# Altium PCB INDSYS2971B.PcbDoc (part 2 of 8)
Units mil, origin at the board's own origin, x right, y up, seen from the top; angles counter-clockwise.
Board outline 6450 x 5820 mil, 6 copper layers (Top Layer, Int1 (PGND), Int2 (AGND), Int3 (Signal), Int4 (PGND), Bottom Layer), stack 70.536 mil thick; 787 components, 431 nets, 2530 pads, 2497 vias.
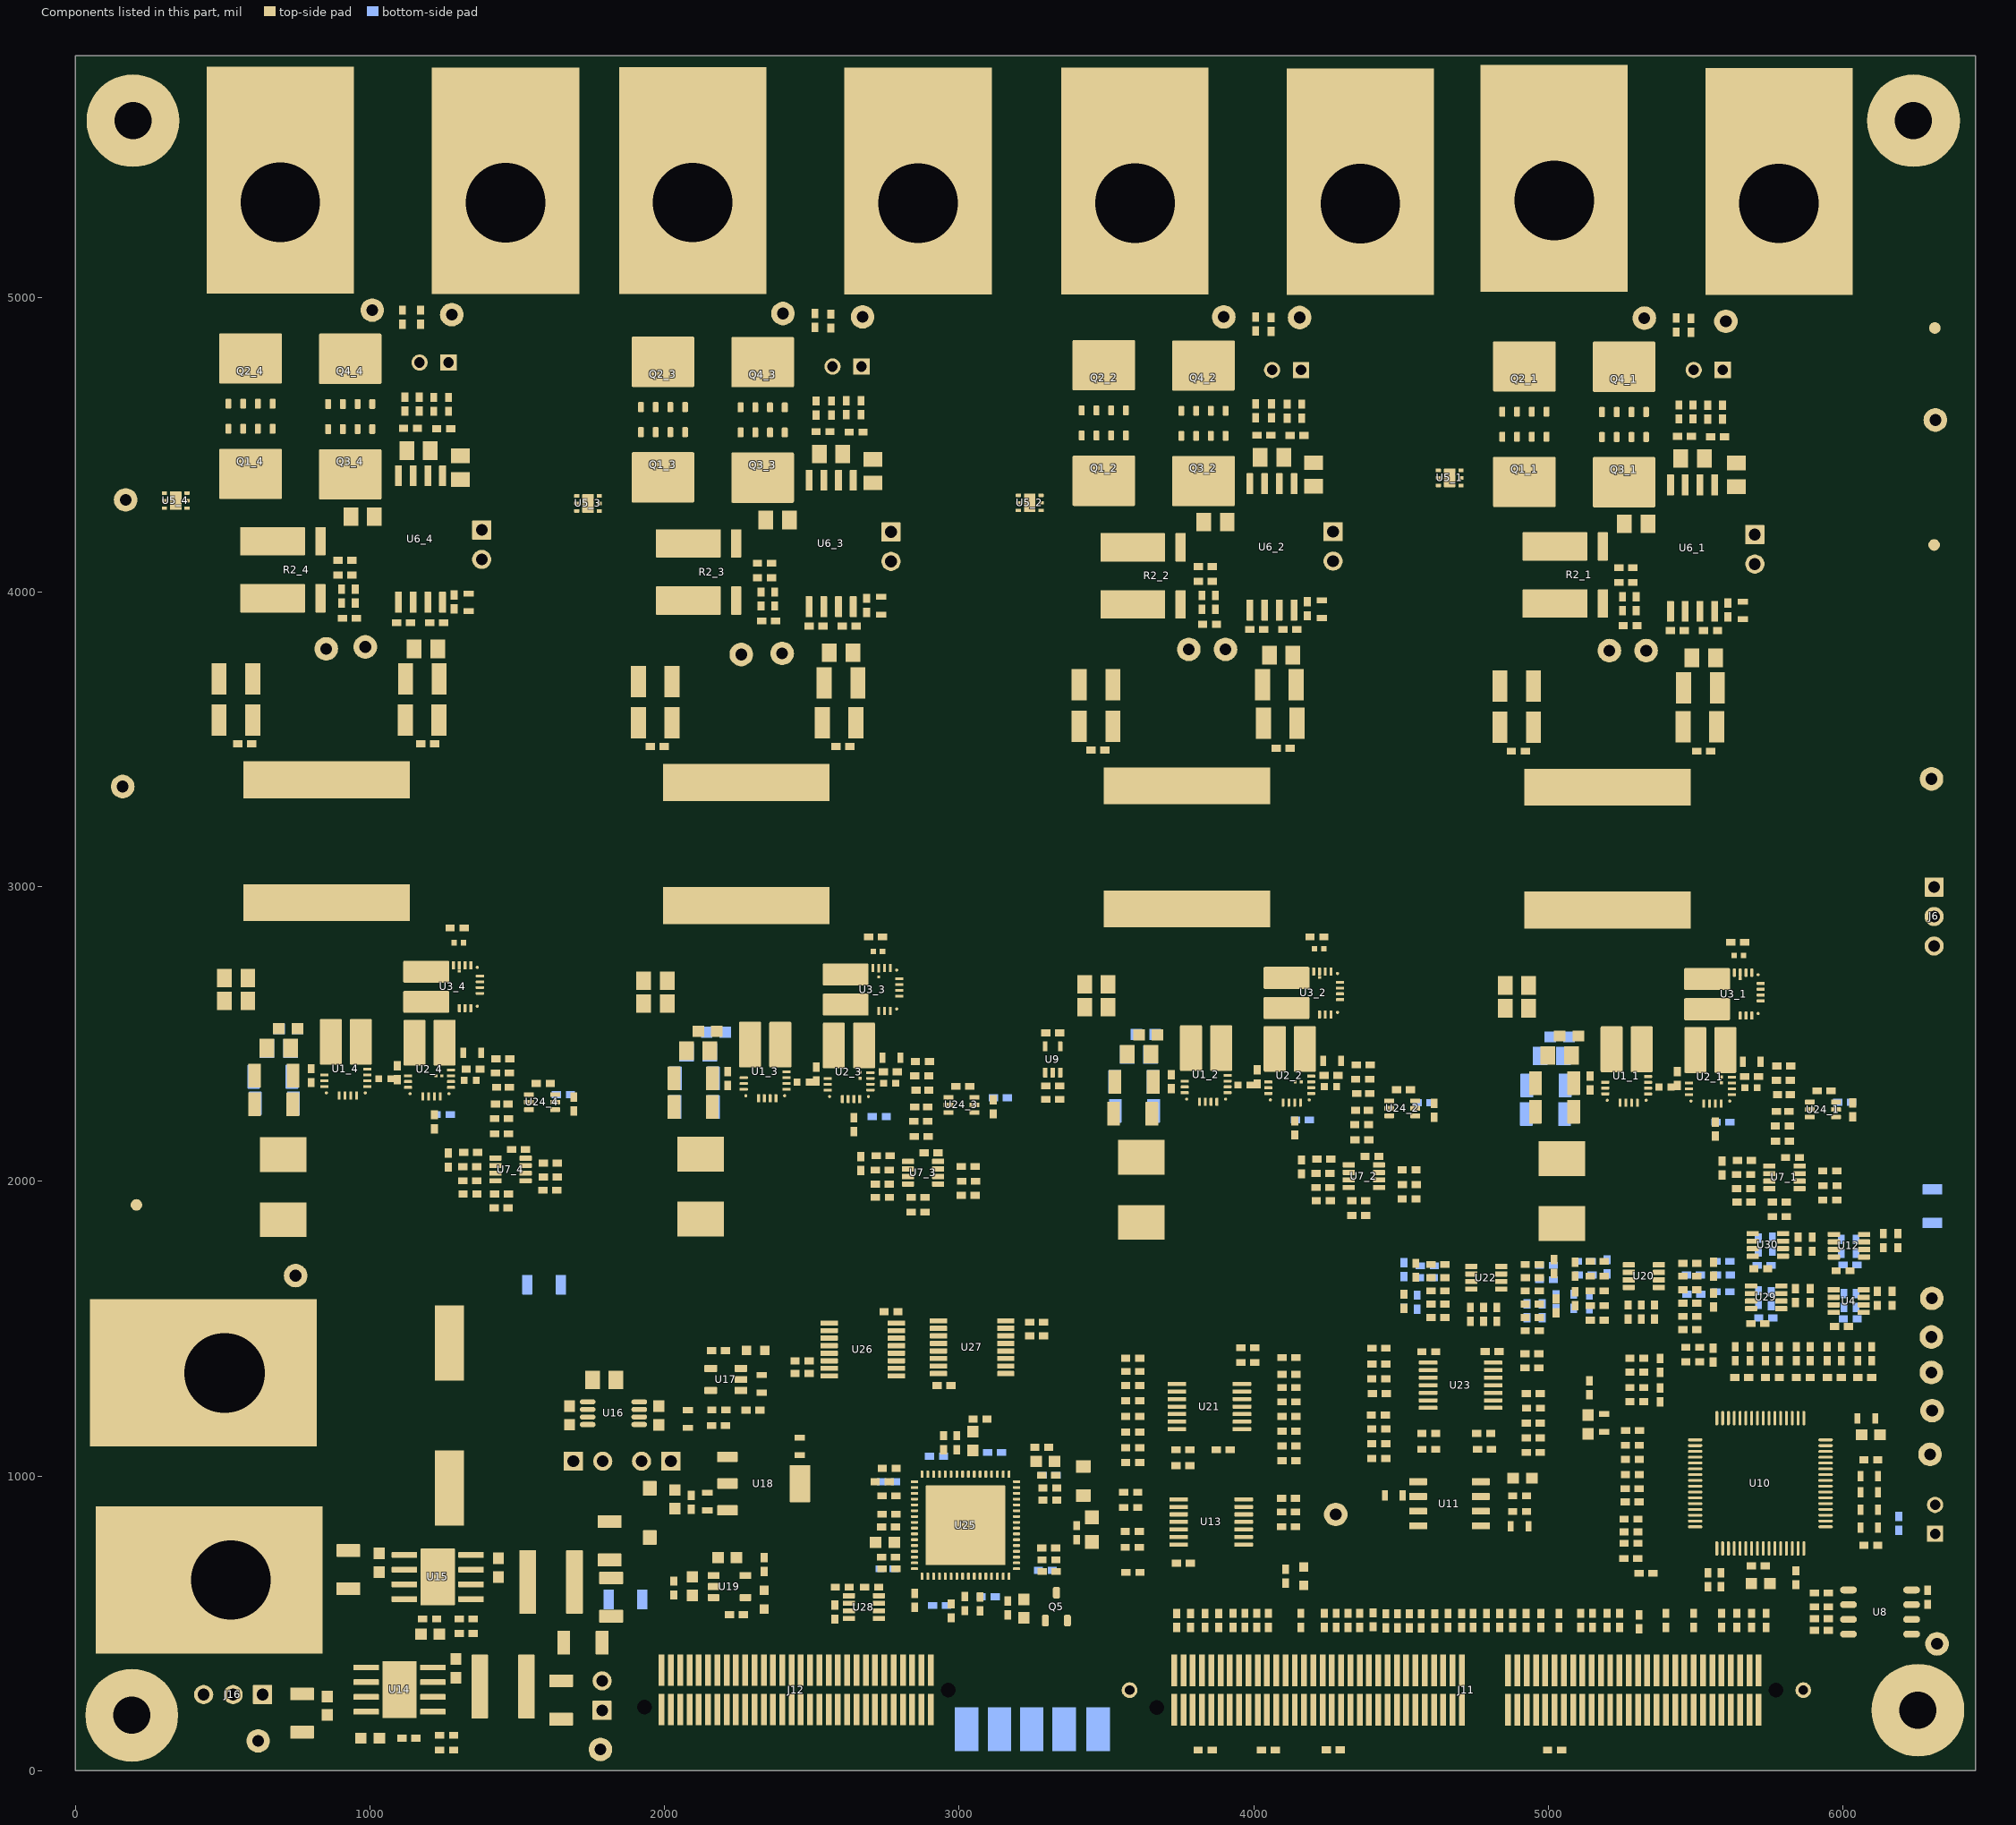
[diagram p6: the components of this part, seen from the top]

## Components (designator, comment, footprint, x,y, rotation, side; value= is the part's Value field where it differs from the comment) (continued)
R28_1 "PCF0402-12-10K0BT1" 0402 5574.72,4527.42 r180 top value=10.0k (schematic designator R28)
R28_2 "PCF0402-12-10K0BT1" 0402 4146.72,4531.42 r180 top value=10.0k (schematic designator R28)
R28_3 "PCF0402-12-10K0BT1" 0402 2650.11,4543.03 r180 top value=10.0k (schematic designator R28)
R28_4 "PCF0402-12-10K0BT1" 0402 1249.72,4554.36 r180 top value=10.0k (schematic designator R28)
R29_1 "PCF0402-12-10K0BT1" 0402 5955.6,1936.76 r180 top value=10.0k (schematic designator R29)
R29_2 "PCF0402-12-10K0BT1" 0402 4527.6,1940.76 r180 top value=10.0k (schematic designator R29)
R29_3 "PCF0402-12-10K0BT1" 0402 3031,1952.37 r180 top value=10.0k (schematic designator R29)
R29_4 "PCF0402-12-10K0BT1" 0402 1610,1970.14 r180 top value=10.0k (schematic designator R29)
R30_1 "CRCW040220K0FKED" 0402 5438.62,3869.5 r0 top value=20.0k (schematic designator R30)
R30_2 "CRCW040220K0FKED" 0402 4010.62,3873.5 r0 top value=20.0k (schematic designator R30)
R30_3 "CRCW040220K0FKED" 0402 2514.01,3885.11 r0 top value=20.0k (schematic designator R30)
R30_4 "CRCW040220K0FKED" 0402 1113.62,3896.44 r0 top value=20.0k (schematic designator R30)
R31_1 "PCF0402-12-10K0BT1" 0402 5590.34,2045.14 r270 top value=10.0k (schematic designator R31)
R31_2 "PCF0402-12-10K0BT1" 0402 4162.34,2049.14 r270 top value=10.0k (schematic designator R31)
R31_3 "PCF0402-12-10K0BT1" 0402 2665.73,2060.75 r270 top value=10.0k (schematic designator R31)
R31_4 "PCF0402-12-10K0BT1" 0402 1265.34,2072.08 r270 top value=10.0k (schematic designator R31)
R32_1 "PCF0402-12-10K0BT1" 0402 5666.43,2071.44 r0 top value=10.0k (schematic designator R32)
R32_2 "PCF0402-12-10K0BT1" 0402 4238.43,2075.44 r0 top value=10.0k (schematic designator R32)
R32_3 "PCF0402-12-10K0BT1" 0402 2741.82,2087.05 r0 top value=10.0k (schematic designator R32)
R32_4 "PCF0402-12-10K0BT1" 0402 1341.43,2098.38 r0 top value=10.0k (schematic designator R32)
R33_1 "CRCW040212K4FKED" 0402 5784.65,1930.14 r0 top value=12.4k (schematic designator R33)
R33_2 "CRCW040212K4FKED" 0402 4356.65,1934.14 r0 top value=12.4k (schematic designator R33)
R33_3 "CRCW040212K4FKED" 0402 2860.04,1945.75 r0 top value=12.4k (schematic designator R33)
R33_4 "CRCW040212K4FKED" 0402 1445.85,1957.08 r0 top value=12.4k (schematic designator R33)
R34_1 "RC1005F104CS" 0402 5663.58,2022.99 r0 top value=100k (schematic designator R34)
R34_2 "RC1005F104CS" 0402 4235.58,2026.99 r0 top value=100k (schematic designator R34)
R34_3 "RC1005F104CS" 0402 2738.97,2038.6 r0 top value=100k (schematic designator R34)
R34_4 "RC1005F104CS" 0402 1338.58,2049.93 r0 top value=100k (schematic designator R34)
R35_1 "PCF0402-12-10K0BT1" 0402 5663.58,1975.38 r0 top value=10.0k (schematic designator R35)
R35_2 "PCF0402-12-10K0BT1" 0402 4235.58,1979.38 r0 top value=10.0k (schematic designator R35)
R35_3 "PCF0402-12-10K0BT1" 0402 2738.97,1990.99 r0 top value=10.0k (schematic designator R35)
R35_4 "PCF0402-12-10K0BT1" 0402 1338.58,2002.32 r0 top value=10.0k (schematic designator R35)
R36 "CRCW04020000Z0ED" 0402 5690,510.14 r270 top value=0
R37 "CRCW04020000Z0ED" 0402 5493.78,510.14 r90 top value=0
R38 "CRCW04020000Z0ED" 0402 5640,510.14 r90 top value=0
R39 "CRCW04020000Z0ED" 0402 5399.29,510.14 r90 top value=0
R40 "CRCW04020000Z0ED" 0402 5308.43,505.14 r90 top value=0
R41 "CRCW04020000Z0ED" 0402 5588.27,510.14 r90 top value=0
R42 "CRCW04020000Z0ED" 0402 5241.81,510.14 r90 top value=0
R43 "CRCW04020000Z0ED" 0402 5200,510.14 r90 top value=0
R44 "CRCW04020000Z0ED" 0402 5150,510.14 r90 top value=0
R45 "CRCW04020000Z0ED" 0402 5110,510.14 r90 top value=0
R46 "CRCW04020000Z0ED" 0402 5036.34,509.28 r90 top value=0
R47 "CRCW040222R0JNED" 0402 4975,509.28 r270 top value=22
R48 "CRCW04020000Z0ED" 0402 4790,509.28 r90 top value=0
R49 "CRCW040222R0JNED" 0402 4925,509.28 r270 top value=22
R50 "CRCW04020000Z0ED" 0402 4745,509.28 r90 top value=0
R51 "CRCW040222R0JNED" 0402 4878.86,509.28 r270 top value=22
R52 "CRCW040222R0JNED" 0402 5332.29,670.14 r180 top value=22
R53 "CRCW040222R0JNED" 0402 4835,509.28 r270 top value=22
R54 "CRCW040222R0JNED" 0402 4614.73,508.66 r90 top value=22
R55 "CRCW04020000Z0ED" 0402 4705.76,509.28 r90 top value=0
R56 "CRCW04020000Z0ED" 0402 4660,509.28 r90 top value=0
R57 "ERA-2AEB102X" 0402 4107.95,660.14 r270 top value=1.00k
R58 "CRCW040222R0JNED" 0402 5926.82,555.79 r0 top value=22
R59 "CRCW040222R0JNED" 0402 4568.31,508.66 r270 top value=22
R60 "CRCW040222R0JNED" 0402 5926.82,515.79 r0 top value=22
R61 "CRCW040222R0JNED" 0402 4528.31,508.66 r270 top value=22
R62 "CRCW040222R0JNED" 0402 5926.82,475.79 r0 top value=22
R63 "CRCW040222R0JNED" 0402 4488.31,508.66 r270 top value=22
R64 "CRCW040222R0JNED" 0402 5926.82,602.87 r0 top value=22
R65 "CRCW040222R0JNED" 0402 4448.31,508.66 r270 top value=22
R66 "CRCW040222R0JNED" 0402 4359.92,510.14 r270 top value=22
R67 "CRCW040222R0JNED" 0402 4320,510.14 r270 top value=22
R68 "CRCW040222R0JNED" 0402 4280,510.14 r270 top value=22
R69 "CRCW040222R0JNED" 0402 4240,510.14 r270 top value=22
R70 "CRCW04020000Z0ED" 0402 5494.77,1616.74 r180 bottom value=0
R71 "CRCW040222R0JNED" 0402 4160,510.14 r90 top value=22
R72 "CRCW040222R0JNED" 0402 4050,510.14 r270 top value=22
R73 "CRCW040222R0JNED" 0402 4010,510.14 r270 top value=22
R74 "CRCW040222R0JNED" 0402 3970,510.14 r270 top value=22
R75 "CRCW040222R0JNED" 0402 3930,510.14 r270 top value=22
R76 "CRCW0402120RJNED" 0402 6190.14,838.94 r270 bottom value=120
R77 "PCF0402-12-10K0BT1" 0402 3317.5,2323.72 r0 top value=10.0k
R78 "CRCW0402499RFKED" 0402 6098.27,1414.56 r270 top value=499
R79 "PCF0402-12-10K0BT1" 0402 5280.95,853.62 r180 top value=10.0k
R80 "PCF0402-12-10K0BT1" 0402 5280.95,771.33 r180 top value=10.0k
R81 "CRCW0402499RFKED" 0402 6051.02,1414.56 r270 top value=499
R82 "PCF0402-12-10K0BT1" 0402 5280.95,810.7 r180 top value=10.0k
R83 "CRCW0402499RFKED" 0402 5994.65,1414.56 r270 top value=499
R84 "PCF0402-12-10K0BT1" 0402 5541.97,647.79 r270 top value=10.0k
R85 "CRCW0402499RFKED" 0402 5947.4,1414.56 r270 top value=499
R86 "CRCW0402499RFKED" 0402 5889.29,1414.56 r270 top value=499
R87 "CRCW0402499RFKED" 0402 5842.05,1414.56 r270 top value=499
R88 "CRCW04020000Z0ED" 0402 5139.95,1299.02 r270 top value=0
R89 "PCF0402-12-10K0BT1" 0402 5280,720.14 r0 top value=10.0k
R90 "CRCW0402499RFKED" 0402 5784.65,1414.56 r270 top value=499
R91 "CRCW0402499RFKED" 0402 5737.4,1414.56 r270 top value=499
R92 "PCF0402-12-10K0BT1" 0402 5585.98,647.79 r90 top value=10.0k
R93 "CRCW0402499RFKED" 0402 5684.8,1414.56 r270 top value=499
R94 "CRCW0402499RFKED" 0402 5634.8,1414.56 r270 top value=499
R95 "CRCW0402499RFKED" 0402 5490.59,1436.92 r0 top value=499
R96 "CRCW0402499RFKED" 0402 5490.59,1387.55 r0 top value=499
R97 "CRCW0402499RFKED" 0402 5300.59,1399.91 r0 top value=499
R98 "CRCW0402499RFKED" 0402 5300.59,1352.66 r0 top value=499
R99 "PCF0402-12-10K0BT1" 0402 6095,765.14 r180 top value=10.0k
R100 "CRCW0402499RFKED" 0402 5300.59,1300.03 r0 top value=499
R101 "CRCW04020000Z0ED" 0402 5841.02,654.56 r90 top value=0
R102 "CRCW0402499RFKED" 0402 5300.59,1252.78 r0 top value=499
R103 "PCF0402-12-10K0BT1" 0402 5284.8,956.69 r180 top value=10.0k
R104 "PCF0402-12-10K0BT1" 0402 5285.55,1004.56 r180 top value=10.0k
R105 "PCF0402-12-10K0BT1" 0402 5286.14,1154.56 r180 top value=10.0k
R106 "CRCW04020000Z0ED" 0402 4902.71,879.49 r0 top value=0
R107 "ERJ-2BQFR22X" 0402 4902.71,932.76 r180 top value=0.22
R108 "PCF0402-12-10K0BT1" 0402 5284.8,911.8 r0 top value=10.0k
R109 "PCF0402-12-10K0BT1" 0402 5285.55,1056.76 r0 top value=10.0k
R110 "PCF0402-12-10K0BT1" 0402 5285.55,1104.56 r0 top value=10.0k
R111 "CRCW040222R0JNED" 0402 4118.23,827.92 r0 top value=22
R112 "CRCW040220K0FKED" 0402 3582.44,944.53 r180 top value=20.0k
R113 "CRCW04020000Z0ED" 0402 4118.23,878.19 r180 top value=0
R114 "CRCW040220K0FKED" 0402 3582.44,893.35 r180 top value=20.0k
R115 "CRCW0402200KFKED" 0402 3587.44,758.23 r180 top value=200k
R116 "PCF0402-12-10K0BT1" 0402 3590.09,673.02 r180 top value=10.0k
R117 "CRCW04020000Z0ED" 0402 4118.23,924.02 r0 top value=0
R118 "CRCW040240K2FKED" 0402 1260,70.14 r0 top value=40.2k
R119 "MCR01MZPF6982" 0402 1325.81,514.74 r0 top value=69.8k
R120 "RC0402FR-07100KL" 0402 1260,120.14 r0 top value=100k
R121 "RC0402FR-07100KL" 0402 1325.81,465.25 r180 top value=100k
R122 "ERJPA2F1002X" 0402 1131.5,110.14 r0 top value=10.0k
R123 "ERJPA2F1002X" 0402 1202.24,514.74 r0 top value=10.0k
R124 "RC0603FR-0726K1L" 0603 1000,110.14 r180 top value=26.1k
R125 "RC0603FR-0726K1L" 0603 1203.92,463.4 r180 top value=26.1k
R126 "ERA-2AEB102X" 0402 2183.12,1425.83 r180 top value=1.00k
R127 "PCF0402-12-10K0BT1" 0402 2300.17,1223.45 r0 top value=10.0k
R128 "PCF0402-12-10K0BT1" 0402 2184,1224.34 r0 top value=10.0k
R129 "CRCW12060000Z0EAC" FP-CRCW12060000Z0EAC_1206-MFG 1590.72,1649.44 r0 bottom value=0
R130 "CRCW12060000Z0EAC" FP-CRCW12060000Z0EAC_1206-MFG 6304.41,1915.9 r90 bottom value=0
R131 "ERA-2AEB102X" 0402 2338.06,699.28 r90 top value=1.00k
R132 "CRCW12060000Z0EAC" FP-CRCW12060000Z0EAC_1206-MFG 1867.09,580.82 r0 bottom value=0
R133 "CRCW0402499RFKED" 0402 5560.92,1701.78 r270 top value=499
R134 "CRCW040241K2FKED" 0402 5481.06,1678.44 r0 top value=41.2k
R135 "CRCW040249K9FKED" 0402 5480.92,1631.78 r180 top value=49.9k
R136 "CRCW040249K9FKED" 0402 5480.92,1586.78 r180 top value=49.9k
R137 "CRCW040220K0FKED" 0402 3588.94,1201.83 r180 top value=20.0k
R138 "CRCW0402499RFKED" 0402 5560.92,1596.78 r90 top value=499
R139 "CRCW04020000Z0ED" 0402 5360.92,1556.78 r270 top value=0
R140 "CRCW040249K9FKED" 0402 3588.94,1255.52 r0 top value=49.9k
R141 "CRCW040241K2FKED" 0402 5480.92,1541.78 r0 top value=41.2k
R142 "CRCW040249K9FKED" 0402 3588.94,1306.7 r0 top value=49.9k
R143 "CRCW040220K0FKED" 0402 3590,1355.14 r0 top value=20.0k
R144 "CRCW0402499RFKED" 0402 5090.92,1701.78 r270 top value=499
R145 "CRCW040241K2FKED" 0402 5166.06,1728.44 r180 top value=41.2k
R146 "CRCW040249K9FKED" 0402 5166.06,1678.44 r0 top value=49.9k
R147 "CRCW040249K9FKED" 0402 5166.06,1628.44 r0 top value=49.9k
R148 "CRCW040220K0FKED" 0402 3588.94,1045.52 r180 top value=20.0k
R149 "CRCW0402499RFKED" 0402 5090.92,1601.78 r90 top value=499
R150 "CRCW040241K2FKED" 0402 5166.06,1578.44 r180 top value=41.2k
R151 "CRCW04020000Z0ED" 0402 5315.92,1556.78 r270 top value=0
R152 "CRCW040249K9FKED" 0402 3588.94,1095.52 r0 top value=49.9k
R153 "CRCW040249K9FKED" 0402 3896.58,1089.15 r180 top value=49.9k
R154 "CRCW040220K0FKED" 0402 3759.73,1089.15 r180 top value=20.0k
R155 "CRCW0402499RFKED" 0402 5019.83,1711.34 r270 top value=499
R156 "CRCW040241K2FKED" 0402 4945.74,1672.96 r0 top value=41.2k
R157 "CRCW040249K9FKED" 0402 4945.43,1628.12 r180 top value=49.9k
R158 "CRCW040220K0FKED" 0402 4119.73,1251.83 r0 top value=20.0k
R159 "CRCW040249K9FKED" 0402 4945.43,1583.12 r180 top value=49.9k
R160 "CRCW040249K9FKED" 0402 4119.73,1201.83 r180 top value=49.9k
R161 "CRCW0402499RFKED" 0402 5026.16,1576.96 r90 top value=499
R162 "CRCW04020000Z0ED" 0402 4825.43,1548.12 r270 top value=0
R163 "CRCW040249K9FKED" 0402 4119.73,1151.83 r180 top value=49.9k
R164 "CRCW040241K2FKED" 0402 4945.43,1493.12 r0 top value=41.2k
R165 "CRCW040220K0FKED" 0402 4119.73,1101.83 r180 top value=20.0k
R166 "CRCW0402499RFKED" 0402 4550.43,1698.12 r270 top value=499
R167 "CRCW040220K0FKED" 0402 4120,1300.14 r0 top value=20.0k
R168 "CRCW040241K2FKED" 0402 4625.43,1718.12 r180 top value=41.2k
R169 "CRCW040249K9FKED" 0402 4120,1345.14 r180 top value=49.9k
R170 "CRCW040249K9FKED" 0402 4625.43,1673.12 r0 top value=49.9k
R171 "CRCW040249K9FKED" 0402 4119.73,1401.83 r180 top value=49.9k
R172 "CRCW040249K9FKED" 0402 4625.43,1628.12 r0 top value=49.9k
R173 "CRCW0402499RFKED" 0402 4510,1593.12 r90 top value=499
R174 "CRCW040241K2FKED" 0402 4625.43,1538.12 r180 top value=41.2k
R175 "CRCW04020000Z0ED" 0402 4780.43,1548.12 r270 top value=0
R176 "CRCW040220K0FKED" 0402 3979.73,1435.52 r180 top value=20.0k
R177 "PCF0402-12-10K0BT1" 0402 4424.45,1109.72 r180 top value=10.0k
R178 "PCF0402-12-10K0BT1" 0402 4426.38,1279.72 r180 top value=10.0k
R179 "CRCW040240K2FKED" 0402 4424.45,1159.72 r0 top value=40.2k
R180 "CRCW040240K2FKED" 0402 4424.45,1329.72 r0 top value=40.2k
R181 "CRCW040240K2FKED" 0402 4424.69,1379.72 r0 top value=40.2k
R182 "CRCW040240K2FKED" 0402 4424.45,1059.72 r0 top value=40.2k
R183 "PCF0402-12-10K0BT1" 0402 4594.37,1144.44 r180 top value=10.0k
R184 "PCF0402-12-10K0BT1" 0402 4594.37,1421.56 r180 top value=10.0k
R185 "PCF0402-12-10K0BT1" 0402 4949.33,1179.72 r0 top value=10.0k
R186 "PCF0402-12-10K0BT1" 0402 4949.83,1230.21 r0 top value=10.0k
R187 "CRCW040240K2FKED" 0402 4949.33,1129.72 r180 top value=40.2k
R188 "CRCW040240K2FKED" 0402 4949.33,1279.72 r180 top value=40.2k
R189 "CRCW040240K2FKED" 0402 4949.33,1079.72 r180 top value=40.2k
R190 "CRCW040240K2FKED" 0402 4944.21,1367.1 r180 top value=40.2k
R191 "PCF0402-12-10K0BT1" 0402 4944.21,1414.74 r0 top value=10.0k
R192 "PCF0402-12-10K0BT1" 0402 4781.06,1144.44 r0 top value=10.0k
R193_1 "CRCW0402187RFKED" 0402 5797.69,2342.84 r180 top value=187 (schematic designator R193)
R193_2 "CRCW0402187RFKED" 0402 4369.69,2346.84 r180 top value=187 (schematic designator R193)
R193_3 "CRCW0402187RFKED" 0402 2873.08,2358.45 r180 top value=187 (schematic designator R193)
R193_4 "CRCW0402187RFKED" 0402 1449.06,2367.84 r180 top value=187 (schematic designator R193)
R194 "CRCW040222R0JNED" 0402 4405,511.75 r270 top value=22
R195 "CRCW040222R0JNED" 0402 3881.08,509.28 r270 top value=22
R196 "CRCW040222R0JNED" 0402 3785.24,509.28 r90 top value=22
R197 "CRCW040222R0JNED" 0402 3835,509.28 r270 top value=22
R198 "CRCW040222R0JNED" 0402 3738.6,509.28 r90 top value=22
R199 "CRCW04020000Z0ED" 0402 5592.87,2200.95 r0 bottom value=0
R200 "CRCW04020000Z0ED" 0402 4165.44,2208.6 r0 bottom value=0
R201 "CRCW04020000Z0ED" 0402 2728.83,2220.33 r0 bottom value=0
R202 "CRCW04020000Z0ED" 0402 1248.33,2226.7 r0 bottom value=0
R203 "CRCW04020000Z0ED" 0402 6006.29,2268.29 r180 bottom value=0
R204 "CRCW04020000Z0ED" 0402 4578.29,2267.4 r180 bottom value=0
R205 "CRCW04020000Z0ED" 0402 3140,2283.53 r0 bottom value=0
R206 "CRCW04020000Z0ED" 0402 1656.45,2294.5 r180 bottom value=0
R207 "CRCW06031R00JNEA" 0603 3292.6,1049.14 r180 top value=1.0
R208 "CRCW040222R0JNED" 0402 3307.89,958.85 r0 top value=22
R209 "CRCW040222R0JNED" 0402 3303.62,1002.16 r0 top value=22
R210 "CRCW04020000Z0ED" 0402 6045,1595.58 r270 bottom value=0
R211 "CRCW04020000Z0ED" 0402 6045,1779.07 r270 bottom value=0
R212 "CRCW04020000Z0ED" 0402 5757.14,1601.36 r270 bottom value=0
R213 "CRCW04020000Z0ED" 0402 5761.02,1786.8 r270 bottom value=0
R214 "CRCW04020000Z0ED" 0402 6004.14,1595.32 r270 bottom value=0
R215 "CRCW04020000Z0ED" 0402 5995,1779.07 r270 bottom value=0
R216 "CRCW04020000Z0ED" 0402 5714.16,1605.58 r270 bottom value=0
R217 "CRCW040222R0JNED" 0402 2761.69,932.87 r180 top value=22
R218 "CRCW04020000Z0ED" 0402 5713.15,1784.3 r270 bottom value=0
R219 "CRCW040222R0JNED" 0402 2738.35,980.57 r180 top value=22
R220 "CRCW04020000Z0ED" 0402 5593.04,1625.41 r0 bottom value=0
R221 "PCF0402-12-10K0BT1" 0402 3070.75,1193.47 r0 top value=10.0k
R222 "PCF0402-12-10K0BT1" 0402 2946.65,1113.11 r270 top value=10.0k
R223 "CRCW04020000Z0ED" 0402 5086.71,1593.12 r270 bottom value=0
R224 "PCF0402-12-10K0BT1" 0402 2972.44,542.23 r90 top value=10.0k
R225 "CRCW04020000Z0ED" 0402 5026.16,1590.74 r270 bottom value=0
R226 "CRCW040222R0JNED" 0402 2760.56,724.66 r180 top value=22
R227 "CRCW04020000Z0ED" 0402 4510,1593.12 r270 bottom value=0
R228 "PCF0402-12-10K0BT1" 0402 3399.11,807.93 r90 top value=10.0k
R229 "CRCW040222R0JNED" 0402 2761.69,685.29 r180 top value=22
R230 "PCF0402-12-10K0BT1" 0402 3070.75,565.63 r90 top value=10.0k
R231 "ERA-2AEB102X" 0402 3304.11,755.36 r0 top value=1.00k
R232 "ERA-2AEB102X" 0402 3307.89,918.19 r180 top value=1.00k
R233 "CRCW040222R0JNED" 0402 3304.71,715.48 r0 top value=22
R234 "CRCW040222R0JNED" 0402 3305.93,676.14 r0 top value=22
R235 "CRCW04020000Z0ED" 0402 5595.05,1681.9 r0 bottom value=0
R236 "CRCW04020000Z0ED" 0402 5593.04,1728.44 r0 bottom value=0
R237 "CRCW04020000Z0ED" 0402 5125.41,1681.9 r0 bottom value=0
R238 "CRCW04020000Z0ED" 0402 5122.08,1728.44 r0 bottom value=0
R239 "CRCW04020000Z0ED" 0402 5492.69,1681.9 r180 bottom value=0
R240 "CRCW04020000Z0ED" 0402 3305.59,1002.16 r0 bottom value=0
R241 "CRCW06031R00JNEA" 0603 3046.54,1118.73 r90 top value=1.0
R242 "CRCW04020000Z0ED" 0402 2760,980.57 r180 bottom value=0
R243 "PCF0402-12-10K0BT1" 0402 2466.49,1391 r0 top value=10.0k
R244 "CRCW04020000Z0ED" 0402 4993.91,1666.09 r180 bottom value=0
R245 "CRCW04020000Z0ED" 0402 4993.89,1714.82 r180 bottom value=0
R246 "CRCW04020000Z0ED" 0402 4585.68,1673.12 r0 bottom value=0
R247 "CRCW04020000Z0ED" 0402 4589.61,1713.39 r0 bottom value=0
R248 "CRCW04020000Z0ED" 0402 5200,1710.14 r90 bottom value=0
R249 "CRCW04020000Z0ED" 0402 4927.36,1560.78 r270 bottom value=0
R250 "ERA-2AEB102X" 0402 2578.07,537.94 r90 top value=1.00k
R251 "ERA-2AEB102X" 0402 2603.07,622.94 r0 top value=1.00k
R252 "CRCW04020000Z0ED" 0402 2755,685.14 r180 bottom value=0
R253 "CRCW04020000Z0ED" 0402 3292.6,679.83 r0 bottom value=0
R254 "PCF0402-12-10K0BT1" 0402 3262.56,1475.53 r180 top value=10.0k
R255 "CRCW04020000Z0ED" 0402 6187.31,1798.69 r270 top value=0
R256 "CRCW04020000Z0ED" 0402 5889.5,1612.46 r270 top value=0
R257 "CRCW04020000Z0ED" 0402 5896.45,1786.56 r270 top value=0
R258 "CRCW04020000Z0ED" 0402 5140,1590.25 r270 bottom value=0
R259 "CRCW04020000Z0ED" 0402 4979.28,1560.78 r270 bottom value=0
R260 "CRCW04020000Z0ED" 0402 4510,1700.14 r90 bottom value=0
SH-J2 "60900213421" Wurth_60900213421 1787.64,254.71 r270 top
SH-J3 "60900213421" Wurth_60900213421 1971.46,1050.23 r180 top
SH-J4 "60900213421" Wurth_60900213421 484.1,258.97 r180 top
SH-J5 "60900213421" Wurth_60900213421 1740,1050.25 r180 top
T1 "CXS70-14-C" Panduit_CXS70-14-C 508,1350.14 r0 top
T2 "CXS70-14-C" Panduit_CXS70-14-C 527.83,646.99 r0 top
T3_1 "CXS70-14-C" Panduit_CXS70-14-C 5020,5329.03 r270 top (schematic designator T3)
T3_2 "CXS70-14-C" Panduit_CXS70-14-C 3596.97,5320.71 r270 top (schematic designator T3)
T3_3 "CXS70-14-C" Panduit_CXS70-14-C 2095.39,5322.32 r270 top (schematic designator T3)
T3_4 "CXS70-14-C" Panduit_CXS70-14-C 695,5323.65 r270 top (schematic designator T3)
T4_1 "CXS70-14-C" Panduit_CXS70-14-C 5783.43,5319.35 r270 top (schematic designator T4)
T4_2 "CXS70-14-C" Panduit_CXS70-14-C 4362,5318.35 r270 top (schematic designator T4)
T4_3 "CXS70-14-C" Panduit_CXS70-14-C 2860.39,5319.95 r270 top (schematic designator T4)
T4_4 "CXS70-14-C" Panduit_CXS70-14-C 1460,5321.28 r270 top (schematic designator T4)
TP1 "5000" Keystone5000 747.01,1680.14 r90 top
TP2 "5001" Keystone5001 6301.18,3366.14 r90 top
TP3_1 "5000" Keystone5000 5207.68,3801.64 r180 top (schematic designator TP3)
TP3_2 "5000" Keystone5000 3779.68,3805.64 r180 top (schematic designator TP3)
TP3_3 "5000" Keystone5000 2260.21,3788.34 r180 top (schematic designator TP3)
TP3_4 "5000" Keystone5000 851.24,3807.53 r180 top (schematic designator TP3)
TP4_1 "5001" Keystone5001 5332.36,3801.64 r0 top (schematic designator TP4)
TP4_2 "5001" Keystone5001 3904.36,3805.64 r0 top (schematic designator TP4)
TP4_3 "5001" Keystone5001 2399.09,3792.07 r0 top (schematic designator TP4)
TP4_4 "5001" Keystone5001 983.74,3814.11 r0 top (schematic designator TP4)
TP5_1 "5000" Keystone5000 5326.24,4930.14 r0 top (schematic designator TP5)
TP5_2 "5000" Keystone5000 3898.24,4934.14 r0 top (schematic designator TP5)
TP5_3 "5000" Keystone5000 2401.63,4945.75 r0 top (schematic designator TP5)
TP5_4 "5000" Keystone5000 1007.36,4957.08 r0 top (schematic designator TP5)
TP6_1 "5001" Keystone5001 5603,4919.2 r0 top (schematic designator TP6)
TP6_2 "5001" Keystone5001 4155.72,4931.99 r0 top (schematic designator TP6)
TP6_3 "5001" Keystone5001 2672,4934.26 r0 top (schematic designator TP6)
TP6_4 "5001" Keystone5001 1277.28,4941.79 r0 top (schematic designator TP6)
TP7 "5019" Keystone_5019 3025.15,140.14 r90 bottom
TP8 "5019" Keystone_5019 3246.54,140.14 r90 bottom
TP9 "5001" Keystone5001 6300.7,1471.81 r90 top
TP10 "5001" Keystone5001 6300.7,1351.52 r90 top
TP11 "5000" Keystone5000 620,100.82 r90 top
TP12 "5001" Keystone5001 170,4313.16 r90 top
TP13 "5001" Keystone5001 6314.23,4584.33 r90 top
TP14 "5001" Keystone5001 160,3340.14 r90 top
TP15 "5001" Keystone5001 6296.15,1073.57 r90 top
TP16 "5001" Keystone5001 4278.42,869.61 r90 top
TP17 "5001" Keystone5001 6303.04,1221.85 r90 top
TP18 "5117" Keystone5117 6320,430.15 r90 top
TP19 "5117" Keystone5117 6302.24,1603.02 r90 top
TP20 "5019" Keystone_5019 3471.54,140.14 r90 bottom
TP21 "5019" Keystone_5019 3137.1,140.14 r90 bottom
TP22 "5019" Keystone_5019 3356.54,140.14 r90 bottom
TP23 "5001" Keystone5001 1782.05,71.66 r90 top
U1_1 "LMG3100R017" VBE0015A-MFG 5266.19,2388.46 r180 top (schematic designator U1)
U1_2 "LMG3100R017" VBE0015A-MFG 3838.19,2392.46 r180 top (schematic designator U1)
U1_3 "LMG3100R017" VBE0015A-MFG 2341.58,2404.07 r180 top (schematic designator U1)
U1_4 "LMG3100R017" VBE0015A-MFG 917.57,2413.46 r180 top (schematic designator U1)
U2_1 "LMG3100R017" VBE0015A-MFG 5550.43,2385.74 r180 top (schematic designator U2)
U2_2 "LMG3100R017" VBE0015A-MFG 4122.43,2389.74 r180 top (schematic designator U2)
U2_3 "LMG3100R017" VBE0015A-MFG 2625.82,2401.35 r180 top (schematic designator U2)
U2_4 "LMG3100R017" VBE0015A-MFG 1201.81,2410.74 r180 top (schematic designator U2)
U3_1 "LMG3100R017" VBE0015A-MFG 5599.23,2635.51 r270 top (schematic designator U3)
U3_2 "LMG3100R017" VBE0015A-MFG 4171.23,2639.51 r270 top (schematic designator U3)
U3_3 "LMG3100R017" VBE0015A-MFG 2674.62,2651.12 r270 top (schematic designator U3)
U3_4 "LMG3100R017" VBE0015A-MFG 1250.61,2660.51 r270 top (schematic designator U3)
U4 "INA241A5IDDF" DDF0008A-MFG 6020.06,1593.65 r0 top
U5_1 "TVS0500DRVR" DRV0006A 4665.39,4387.69 r0 top (schematic designator U5)
U5_2 "TVS0500DRVR" DRV0006A 3239.46,4303.09 r0 top (schematic designator U5)
U5_3 "TVS0500DRVR" DRV0006A 1740,4301.1 r0 top (schematic designator U5)
U5_4 "TVS0500DRVR" DRV0006A 340,4310.49 r0 top (schematic designator U5)
U6_1 "TPSI3050DWZR" DWZ0008A-MFG 5490,4149.5 r90 top (schematic designator U6)
U6_2 "TPSI3050DWZR" DWZ0008A-MFG 4062,4153.5 r90 top (schematic designator U6)
U6_3 "TPSI3050DWZR" DWZ0008A-MFG 2565.39,4165.11 r90 top (schematic designator U6)
U6_4 "TPSI3050DWZR" DWZ0008A-MFG 1171.1,4180.41 r90 top (schematic designator U6)
U7_1 "LM393BIDDFR" DDF0008A-MFG 5801.98,2013.65 r180 top (schematic designator U7)
U7_2 "LM393BIDDFR" DDF0008A-MFG 4373.98,2017.65 r180 top (schematic designator U7)
U7_3 "LM393BIDDFR" DDF0008A-MFG 2877.37,2029.25 r180 top (schematic designator U7)
U7_4 "LM393BIDDFR" DDF0008A-MFG 1476.98,2040.58 r180 top (schematic designator U7)
U8 "THVD1426D" D0008A_N 6126.45,538.22 r0 top
U9 "TMP235DCK" DCK0005A_N 3317.5,2413.72 r90 top
U10 "ADS8588SIPMR" PM0064A_L 5720,975.14 r0 top
U11 "REF54250QDRQ1" D0008A-MFG 4664.45,905.69 r0 top
U12 "INA241A5IDDF" DDF0008A-MFG 6020.93,1781.57 r0 top
U13 "LM324BIPWR" PW0014A-MFG 3855.71,844.02 r0 top
U14 "LMR38010FDDAR" DDA0008E-MFG 1100,275.11 r0 top
U15 "LMR38010FDDAR" DDA0008E-MFG 1229.51,657.07 r0 top
U16 "TL7660CDGKR" DGK0008A_N 1826.21,1213.01 r0 top
U17 "TPS7A2033PDBVR" DBV0005A-MFG 2207.62,1327.77 r180 top
U18 "TLV1117LV30DCYR" DCY0004A_N 2336.34,974.23 r0 top
U19 "TPS73633DBVR" DBV0005A_N 2220.17,624.71 r0 top
U20 "OPA2186DDFR" DDF0008A-MFG 5324.39,1678.44 r180 top
U21 "LM324BIPWR" PW0014A-MFG 3849.73,1235.52 r0 top
U22 "OPA2186DDFR" DDF0008A-MFG 4789.36,1672.96 r180 top
U23 "LM324BIPWR" PW0014A-MFG 4702.55,1308.02 r0 top
U24_1 "SN74LVC2G34DCKR" DCK0006A_N 5932.39,2243.91 r180 top (schematic designator U24)
U24_2 "SN74LVC2G34DCKR" DCK0006A_N 4504.39,2247.91 r180 top (schematic designator U24)
U24_3 "SN74LVC2G34DCKR" DCK0006A_N 3007.79,2259.52 r180 top (schematic designator U24)
U24_4 "SN74LVC2G34DCKR" DCK0006A_N 1583.77,2268.91 r180 top (schematic designator U24)
U25 "AFE871H4RGCT" RGC0064P-MFG 3021.54,832.93 r0 top
U26 "TMUX4053PWR" PW0016A-MFG 2672.65,1429.39 r0 top
U27 "TMUX4053PWR" PW0016A-MFG 3043.94,1437.14 r180 top
U28 "OPA2186DDFR" DDF0008A-MFG 2676.41,555.02 r0 top
U29 "INA241A5IDDF" DDF0008A-MFG 5739.88,1606.44 r0 top
U30 "INA241A5IDDF" DDF0008A-MFG 5745.63,1784.3 r0 top
ZZ1 "This Assembly Note is for PCB labels only" AssemblyNoteLabel 5246.01,3250 r180 bottom
ZZ2 "These assemblies are ESD sensitive, ESD precautions shall be observed." AssemblyNote 5246.01,3175.64 r180 bottom
ZZ3 "These assemblies must be clean and free from flux and all contaminants. Use of no clean flux is not acceptable." AssemblyNote 5247.51,3100 r180 bottom
ZZ4 "These assemblies must comply with workmanship standards IPC-A-610 Class 2, unless otherwise specified." AssemblyNote 5252.47,3030 r180 bottom

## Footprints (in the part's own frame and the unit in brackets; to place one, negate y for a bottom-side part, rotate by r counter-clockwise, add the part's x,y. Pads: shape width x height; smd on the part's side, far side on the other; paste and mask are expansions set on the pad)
0402 [mm] "0402 from SM-752 data"
  rect 0.8x0.6 smd: 1(-0.6,0) 2(0.6,0)
  silkscreen extent -1.22,-0.52 1.22,0.52, body extent -0.55,-0.3 0.55,0.3, height 0.6
0603 [mm] "0603 from SM-752 data"
  rect 1x0.95 smd: 1(-0.8,0) 2(0.8,0)
  silkscreen extent -1.52,-0.69 1.52,0.69, body extent -0.87,-0.47 0.87,0.47, height 1
0603S [mil]
  rect 20x35 smd: 1(-30,0) 2(30,0)
  body extent -34,-19 34,19, height 39
0805_HV [mil] "0805 with 30mil clearance between pads"
  rect 50x63 smd: 1(-40,0) 2(40,0)
  silkscreen extent -74,-40 74,40, body extent -43,-29 43,29, height 57
1210_270 [mm] "1210"
  rect 1.3x2.7 smd: 1(-1.45,0) 2(1.45,0)
  silkscreen extent -2.32,-1.57 2.32,1.57, body extent -1.7,-1.35 1.7,1.35, height 2.7
1806_HighSpeed [mm] "Wurth recommended land pattern"
  rrect8% 1.25x1.2 smd: 1(-2.125,0) 2(2.125,0)
  silkscreen extent -1.5,-1 1.5,1, body extent -2.25,-0.8 2.25,0.8, height 1.61
6125FA [mm] "Cooper Bussman 6125FA Brick Fuses, recommended land pattern OC-2531 Rev. I 3/07"
  rect 3x4 smd: 1(-2.8,0) 2(2.8,0)
  silkscreen extent -4.58,-2.27 4.57,2.28, body extent -3.17,-1.42 3.17,1.41, height 2.84
AssemblyNote [mil] "Assembly Note"
AssemblyNoteLabel [mil] "Assembly Note for PCB Labels"
CE_Mark_5mm [mil] "Minimum text height for CE Mark"
  silkscreen extent -138,-98 138,98
controlCARD-120HSEC [mm] "Pads are not numbered according to Samtec datasheet."
  rect 0.5x2.724 smd: 1(-23.357,-1.678) 2(-23.357,1.722) 3(-22.557,-1.678) 4(-22.557,1.722) 5(-21.757,-1.678) 6(-21.757,1.722) 7(-20.957,-1.678) 8(-20.957,1.722) 9(-20.157,-1.678) 10(-20.157,1.722) 11(-19.357,-1.678) 12(-19.357,1.722) 13(-18.557,-1.678) 14(-18.557,1.722) 15(-17.757,-1.678) 16(-17.757,1.722) 17(-16.957,-1.678) 18(-16.957,1.722) 19(-16.157,-1.678) 20(-16.157,1.722) 21(-15.357,-1.678) 22(-15.357,1.722) 23(-14.557,-1.678) 24(-14.557,1.722) 25(-13.757,-1.678) 26(-13.757,1.722) 27(-12.957,-1.678) 28(-12.957,1.722) 29(-12.157,-1.678) 30(-12.157,1.722) 31(-11.357,-1.678) 32(-11.357,1.722) 33(-10.557,-1.678) 34(-10.557,1.722) 35(-9.757,-1.678) 36(-9.757,1.722) 37(-8.957,-1.678) 38(-8.957,1.722) 39(-8.157,-1.678) 40(-8.157,1.722) 41(-7.357,-1.678) 42(-7.357,1.722) 43(-6.557,-1.678) 44(-6.557,1.722) 45(-5.757,-1.678) 46(-5.757,1.722) 47(-4.957,-1.678) 48(-4.957,1.722) 49(-4.157,-1.678) 50(-4.157,1.722) 51(-3.357,-1.678) 52(-3.357,1.722) 53(-2.557,-1.678) 54(-2.557,1.722) 55(-1.757,-1.678) 56(-1.757,1.722) 57(2.243,-1.678) 58(2.243,1.722) 59(3.043,-1.678) 60(3.043,1.722) 61(3.843,-1.678) 62(3.843,1.722) 63(4.643,-1.678) 64(4.643,1.722) 65(5.443,-1.678) 66(5.443,1.722) 67(6.243,-1.678) 68(6.243,1.722) 69(7.043,-1.678) 70(7.043,1.722) 71(7.843,-1.678) 72(7.843,1.722) 73(8.643,-1.678) 74(8.643,1.722) 75(9.443,-1.678) 76(9.443,1.722) 77(10.243,-1.678) 78(10.243,1.722) 79(11.043,-1.678) 80(11.043,1.722) 81(11.843,-1.678) 82(11.843,1.722) 83(12.643,-1.678) 84(12.643,1.722) 85(13.443,-1.678) 86(13.443,1.722) 87(14.243,-1.678) 88(14.243,1.722) 89(15.043,-1.678) 90(15.043,1.722) 91(15.843,-1.678) 92(15.843,1.722) 93(16.643,-1.678) 94(16.643,1.722) 95(17.443,-1.678) 96(17.443,1.722) 97(18.243,-1.678) 98(18.243,1.722) 99(19.043,-1.678) 100(19.043,1.722) 101(19.843,-1.678) 102(19.843,1.722) 103(20.643,-1.678) 104(20.643,1.722) 105(21.443,-1.678) 106(21.443,1.722) 107(22.243,-1.678) 108(22.243,1.722) 109(23.043,-1.678) 110(23.043,1.722) 111(23.843,-1.678) 112(23.843,1.722) 113(24.643,-1.678) 114(24.643,1.722) 115(25.443,-1.678) 116(25.443,1.722) 117(26.243,-1.678) 118(26.243,1.722) 119(27.043,-1.678) 120(27.043,1.722)
  round 0.025 hole 1.27 unplated mask+0.876: 181(-24.857,0.022) 182(28.543,1.522)
  round 1.348 hole 0.84: 185(-27.207,0.022) 186(30.893,0.022)
  silkscreen extent -32.11,-3.86 35.8,3.9, body extent -31.75,-3.48 35.3,3.52, height 12.35
controlCARD-180HSEC-60pinAddon [mm] "Pads are not numbered according to datasheet."
  round 0.025 hole 1.27 unplated mask+0.876: 61(-13.1,0) 62(13.1,1.5)
  rect 0.5x2.724 smd: 121(-11.6,-1.7) 122(-11.6,1.7) 123(-10.8,-1.7) 124(-10.8,1.7) 125(-10,-1.7) 126(-10,1.7) 127(-9.2,-1.7) 128(-9.2,1.7) 129(-8.4,-1.7) 130(-8.4,1.7) 131(-7.6,-1.7) 132(-7.6,1.7) 133(-6.8,-1.7) 134(-6.8,1.7) 135(-6,-1.7) 136(-6,1.7) 137(-5.2,-1.7) 138(-5.2,1.7) 139(-4.4,-1.7) 140(-4.4,1.7) 141(-3.6,-1.7) 142(-3.6,1.7) 143(-2.8,-1.7) 144(-2.8,1.7) 145(-2,-1.7) 146(-2,1.7) 147(-1.2,-1.7) 148(-1.2,1.7) 149(-0.4,-1.7) 150(-0.4,1.7) 151(0.4,-1.7) 152(0.4,1.7) 153(1.2,-1.7) 154(1.2,1.7) 155(2,-1.7) 156(2,1.7) 157(2.8,-1.7) 158(2.8,1.7) 159(3.6,-1.7) 160(3.6,1.7) 161(4.4,-1.7) 162(4.4,1.7) 163(5.2,-1.7) 164(5.2,1.7) 165(6,-1.7) 166(6,1.7) 167(6.8,-1.7) 168(6.8,1.7) 169(7.6,-1.7) 170(7.6,1.7) 171(8.4,-1.7) 172(8.4,1.7) 173(9.2,-1.7) 174(9.2,1.7) 175(10,-1.7) 176(10,1.7) 177(10.8,-1.7) 178(10.8,1.7) 179(11.6,-1.7) 180(11.6,1.7)
  silkscreen extent -14.68,-3.88 14.68,3.88, body extent -14.3,-3.5 14.3,3.5, height 7.95
D0008A-MFG [mm]
  rrect17% 1.55x0.6 smd paste+0 mask+0: 1(-2.7,1.905) 2(-2.7,0.635) 3(-2.7,-0.635) 4(-2.7,-1.905) 5(2.7,-1.905) 6(2.7,-0.635) 7(2.7,0.635) 8(2.7,1.905)
  silkscreen extent -4.17,-2.5 1.5,2.5, body extent -3.57,-2.75 3.57,2.75, height 0.25
D0008A_N [mm] "SOIC, 8-Leads, Body 4.9x3.9mm, Pitch 1.27mm, IPC Medium Density"
  oval 1.45x0.6 smd: 1(-2.725,1.905) 2(-2.725,0.635) 3(-2.725,-0.635) 4(-2.725,-1.905) 5(2.725,-1.905) 6(2.725,-0.635) 7(2.725,0.635) 8(2.725,1.905)
  silkscreen extent -3.3,-2.5 0.9,2.5, body extent -3,-2.45 3,2.45, height 1.63
DBV0005A-MFG [mm]
  rrect17% 1.1x0.6 smd paste+0 mask+0: 1(-1.3,0.95) 2(-1.3,0) 3(-1.3,-0.95) 4(1.3,-0.95) 5(1.3,0.95)
  silkscreen extent -2.58,-1.52 0.87,1.53, body extent -1.95,-1.78 1.95,1.78, height 0.25
DBV0005A_N [mm] "SOT23, 5-Leads, Body 2.9x1.6mm, Pitch 0.95mm, Lead Span 2.8mm, IPC Medium Density"
  rrect17% 1x0.6 smd: 1(-1.375,0.95) 2(-1.375,0) 3(-1.375,-0.95) 4(1.375,-0.95) 5(1.375,0.95)
  silkscreen extent -1.62,-1.55 0.38,1.55, body extent -1.42,-1.46 1.42,1.46, height 1.09
DCK0005A_N [mm] "SOT353, 5-Leads, Body 2x1.3mm, Pitch 0.65mm, Lead Span 2.1mm, IPC Medium Density"
  rrect25% 0.85x0.4 smd: 1(-1.125,0.65) 2(-1.125,0) 3(-1.125,-0.65) 4(1.125,-0.65) 5(1.125,0.65)
  silkscreen extent -1.48,-1.02 0.55,1.1, body extent -1.14,-1 1.14,1, height 0.95
DCK0006A_N [mm] "SOT23, 6-Leads, Body 2x1.3mm, Pitch 0.65mm, Lead Span 2.1mm, IPC Medium Density"
  rrect25% 0.85x0.4 smd: 1(-1.125,0.65) 2(-1.125,0) 3(-1.125,-0.65) 4(1.125,-0.65) 5(1.125,0) 6(1.125,0.65)
  silkscreen extent -1.5,-1.09 0.51,1.09, body extent -1.14,-1 1.14,1, height 0.95
DCY0004A_N [mm] "SOT223/SC73, 4-Leads, Body 6.5x3.5mm, Pitch 2.3mm, Lead Span 7mm, IPC Medium Density"
  rrect11% 1.75x0.9 smd: 1(-3.125,2.3) 2(-3.125,0) 3(-3.125,-2.3)
  rrect6% 1.75x3.2 smd: 4(3.125,0)
  silkscreen extent -3.02,-3.35 1.4,3.47, body extent -3.48,-3.25 3.48,3.25, height 1.68
DDA0008E-MFG [mm]
  rrect20% 2.2x0.5 smd paste-1000 mask+0: 1(-2.875,1.905) 2(-2.875,0.635) 3(-2.875,-0.635) 4(-2.875,-1.905) 5(2.875,-1.905) 6(2.875,-0.635) 7(2.875,0.635) 8(2.875,1.905)
  rrect3% 2.95x4.9 smd paste-1000 mask-1000: 9(0,0)
  silkscreen extent -4.67,-2.83 2,2.83, body extent -4.08,-2.68 4.08,2.68, height 0.25
DDF0008A-MFG [mm]
  rrect22% 1.05x0.45 smd paste+0 mask+0: 1(-1.3,0.975) 2(-1.3,0.325) 3(-1.3,-0.325) 4(-1.3,-0.975) 5(1.3,-0.975) 6(1.3,-0.325) 7(1.3,0.325) 8(1.3,0.975)
  silkscreen extent -2.5,-1.47 0.4,1.48, body extent -1.92,-1.73 1.92,1.73, height 0.25
DGK0008A_N [mm] "TSOP, 8-Leads, Body 3x3mm, Pitch 0.65mm, IPC Medium Density"
  oval 1.35x0.45 smd: 1(-2.225,0.975) 2(-2.225,0.325) 3(-2.225,-0.325) 4(-2.225,-0.975) 5(2.225,-0.975) 6(2.225,-0.325) 7(2.225,0.325) 8(2.225,0.975)
  silkscreen extent -2.75,-1.55 0.95,1.55, body extent -2.45,-1.5 2.45,1.5, height 0.96
DNK0008A [mm] "SON, 8-Leads, Body 5x6mm"
  rrect39% 0.86x0.51 smd paste-0.05 mask-0.05: 1(-2.82,1.905) 2(-2.82,0.635) 3(-2.82,-0.635) 4(-2.82,-1.905) 5(2.82,-1.905) 6(2.82,-0.635) 7(2.82,0.635) 8(2.82,1.905)
  rrect40% 0.25x0.555 on Top Solder: 9(-0.83,2.373) 9(-0.83,-2.373)
  rrect40% 0.25x0.555 on Top Paste: 9(-0.83,2.373) 9(-0.83,-2.373)
  rrect11% 0.95x1.13 on Top Paste: 9(-0.535,1.33) 9(-0.535,0) 9(-0.535,-1.33) 9(0.615,1.33) 9(0.615,0) 9(0.615,-1.33) 9(1.765,1.33) 9(1.765,0) 9(1.765,-1.33)
  rrect3% 3.58x4 on Top Solder: 9(0.75,0)
  rrect5% 4.34x5.4 smd paste-3 mask-3: 9(1.08,0)
  body extent -3.05,-2.55 3.05,2.55, height 1.06
DRV0006A [mm] "SON, 6-Leads, Body 2x2mm, Pitch 0.65mm, Thermal Pad 1.6x1mm, TI Recommended"
  rrect33% 0.45x0.3 smd: 1(-0.975,0.65) 2(-0.975,0) 3(-0.975,-0.65) 4(0.975,-0.65) 5(0.975,0) 6(0.975,0.65)
  rrect14% 1x0.7 on Top Paste: 7(0,-0.45) 7(0,0.45)
  rrect10% 1x1.6 smd paste-0.5: 7(0,0)
  silkscreen extent -1.05,-1.2 1.05,1.2, body extent -1.05,-1.05 1.05,1.05, height 0.81
DWZ0008A-MFG [mm]
  rrect17% 1.8x0.6 smd paste+0 mask+0: 1(-5.45,1.905) 2(-5.45,0.635) 3(-5.45,-0.635) 4(-5.45,-1.905) 5(5.45,-1.905) 6(5.45,-0.635) 7(5.45,0.635) 8(5.45,1.905)
  silkscreen extent -7.02,-2.98 3.8,2.98, body extent -6.45,-3.22 6.45,3.22, height 0.25
FCC_disclaimer [mil]
Fiducial10-20 [mm]
  round 1 smd mask+0.5: 1(0,0)
  Top Layer keep-out circle w1.178: c0,0 r0.5
FP-CRCW0402-e3-IPC_C [mil]
  rect 18.43x18.6 smd paste+0 mask+0: 1(-15.83,0) 2(15.83,0)
  silkscreen extent -25,-27 25,27, body extent -29,-15 29,15, height 10
FP-CRCW0402-e3-MFG [mm]
  rect 0.6x0.6 smd paste+0 mask+0: 1(-0.525,0) 2(0.525,0)
  silkscreen extent -0.52,-0.7 0.53,0.7, body extent -0.92,-0.4 0.92,0.4, height 0.25
FP-CRCW12060000Z0EAC_1206-MFG [mm]
  rrect11% 0.9x1.7 smd paste+0 mask+0: 1(-1.45,0) 2(1.45,0)
  silkscreen extent -0.62,-0.82 0.62,0.82, body extent -1.53,-0.77 1.53,0.77, height 0.65
FP-GRM32EC72A106KE05L_1210-MFG [mm]
  rrect9% 1.1x2.05 smd paste+0 mask+0: 1(-1.65,0) 2(1.65,0)
  silkscreen extent -0.73,-1.35 0.73,1.35, body extent -1.6,-1.25 1.6,1.25, height 2.7
FP-WSLP2726L5000FEA_2726-MFG [mil]
  rrect11% 96x35 smd paste+0 mask+0: 1(-97,127.5) 2(97,127.5)
  rrect4% 96x220 smd paste+0 mask+0: 3(-97,-35) 4(97,-35)
  body extent -149,-149 149,149, height 10
FP-XGL6060-223MEC_SMT2_6MM51_6MM71-MFG [mm]
  rrect7% 1.43x5.5 smd paste+0 mask+0: 1(-2.02,0) 2(2.02,0)
  silkscreen extent -3.95,-3.46 3.35,3.46, body extent -3.45,-3.55 3.45,3.55, height 0.25
IEC_HotSurface_Large [mil]
  silkscreen extent -435,-375 435,378
Johnson_108-0740-001 [mm] "Banana Jack Uninsulated Standard Type"
  round 12 hole 6.858: 1(0,0)
  body extent -4.77,-5.43 4.75,5.57, height 2.39
JST_B2B-EH-A [mm] "Header (Shrouded), 2.5mm, 2x1, TH"
  rect 1.4x1.4 hole 0.9: 1(-1.25,0)
  round 1.4 hole 0.9: 2(1.25,0)
  silkscreen extent -4.2,-2.2 3.75,1.6, body extent -3.75,-2.2 3.75,1.6, height 6
Keystone5000 [mil] "For Keystone 500x miniature loop terminals"
  round 80 hole 40: 1(0,0)
  silkscreen extent -52,-52 52,52, body extent -49,-49 49,49, height 182
Keystone5001 [mil] "For Keystone 500x miniature loop terminals"
  round 80 hole 40: 1(0,0)
  silkscreen extent -52,-52 52,52, body extent -49,-49 49,49, height 182
Keystone5117 [mil] "For Keystone 500x miniature loop terminals"
  round 80 hole 40: 1(0,0)
  silkscreen extent -52,-52 52,52, body extent -49,-49 49,49, height 182
Keystone_1902C [mil] "Hex Standoff, 4-40 threaded, nylon"
  round 1 on Mech4: 0(0,0)
  body extent -145,-126 146,126, height 501
Keystone_5019 [mm] "Test Point, Miniature, SMT"
  rect 3.8x2.03 smd: 1(0,0)
  silkscreen extent -2.31,-1.42 2.31,1.42, body extent -1.91,-1.02 1.9,1.02, height 2.29
Label_650x200 [mil] "Thermal Transfer Label"
  round 1 on Mech14: 0(0,0)
  silkscreen extent -325,-100 325,100, body extent -325,-100 325,100, height 1
LED_LTST-C170_Red [mm] "LITE-ON"
  rect 1.2x1.2 smd: 1(-1.05,0) 2(1.05,0)
  silkscreen extent -1.6,-1 2.2,1, body extent -1.05,-0.67 1.05,0.67, height 1.1
LTST-C171_Blue [mm] "SMD, 2-Leads, Body 2x1.25mm"
  rrect9% 1.1x1.25 smd: 1(-1.25,0) 2(1.25,0)
  body extent -1.05,-0.68 1.05,0.68, height 0.9
Net-Tie_10mil [mil] "10mil net tie, no solder mask opening, no solder paste"
  rect 10x10 smd paste-5 mask-5: 1(-10,0) 2(10,0)
  Top Layer region: -6,5 6,5 6,-5 -6,-5
"NY PMS 440 0025 PH" [mm] "4-40 nylon screw and mounting hole"
  round 8 hole 3.2: 1(0,0)
  body extent -3.3,-3.3 3.3,3.3, height 2.69
Panduit_CXS70-14-C [mil] "Panduit"
  rect 770x500 hole 270 copper offset -74.8,0 paste-99999: 1(0,0)
  body extent -960,-250 310,250, height 684
PM0064A_L [mm] "Thin QFP, 64-Leads, Body 10x10mm, Pitch 0.5mm, IPC High Density"
  oval 1.25x0.25 smd: 1(-5.625,3.75) 2(-5.625,3.25) 3(-5.625,2.75) 4(-5.625,2.25) 5(-5.625,1.75) 6(-5.625,1.25) 7(-5.625,0.75) 8(-5.625,0.25) 9(-5.625,-0.25) 10(-5.625,-0.75) 11(-5.625,-1.25) 12(-5.625,-1.75) 13(-5.625,-2.25) 14(-5.625,-2.75) 15(-5.625,-3.25) 16(-5.625,-3.75) 33(5.625,-3.75) 34(5.625,-3.25) 35(5.625,-2.75) 36(5.625,-2.25) 37(5.625,-1.75) 38(5.625,-1.25) 39(5.625,-0.75) 40(5.625,-0.25) 41(5.625,0.25) 42(5.625,0.75) 43(5.625,1.25) 44(5.625,1.75) 45(5.625,2.25) 46(5.625,2.75) 47(5.625,3.25) 48(5.625,3.75)
  oval 0.25x1.25 smd: 17(-3.75,-5.625) 18(-3.25,-5.625) 19(-2.75,-5.625) 20(-2.25,-5.625) 21(-1.75,-5.625) 22(-1.25,-5.625) 23(-0.75,-5.625) 24(-0.25,-5.625) 25(0.25,-5.625) 26(0.75,-5.625) 27(1.25,-5.625) 28(1.75,-5.625) 29(2.25,-5.625) 30(2.75,-5.625) 31(3.25,-5.625) 32(3.75,-5.625) 49(3.75,5.625) 50(3.25,5.625) 51(2.75,5.625) 52(2.25,5.625) 53(1.75,5.625) 54(1.25,5.625) 55(0.75,5.625) 56(0.25,5.625) 57(-0.25,5.625) 58(-0.75,5.625) 59(-1.25,5.625) 60(-1.75,5.625) 61(-2.25,5.625) 62(-2.75,5.625) 63(-3.25,5.625) 64(-3.75,5.625)
  silkscreen extent -5.65,-4.35 4.35,4.55, body extent -6.01,-6.01 6.01,6.01, height 1.5
PW0014A-MFG [mm]
  rrect29% 1.6x0.35 smd paste-1000 mask+0: 1(-2.8,1.95) 2(-2.8,1.3) 3(-2.8,0.65) 4(-2.8,0) 5(-2.8,-0.65) 6(-2.8,-1.3) 7(-2.8,-1.95) 8(2.8,-1.95) 9(2.8,-1.3) 10(2.8,-0.65) 11(2.8,0) 12(2.8,0.65) 13(2.8,1.3) 14(2.8,1.95)
  silkscreen extent -4.32,-2.55 2.25,2.55, body extent -3.7,-2.8 3.7,2.8, height 0.25
PW0016A-MFG [mm]
  rrect22% 1.5x0.45 smd paste+0 mask+0: 1(-2.9,2.275) 2(-2.9,1.625) 3(-2.9,0.975) 4(-2.9,0.325) 5(-2.9,-0.325) 6(-2.9,-0.975) 7(-2.9,-1.625) 8(-2.9,-2.275) 9(2.9,-2.275) 10(2.9,-1.625) 11(2.9,-0.975) 12(2.9,-0.325) 13(2.9,0.325) 14(2.9,0.975) 15(2.9,1.625) 16(2.9,2.275)
  silkscreen extent -4.37,-2.55 1.78,2.55, body extent -3.75,-2.8 3.75,2.8, height 0.25
RGC0064P-MFG [mm]
  rrect42% 0.6x0.24 smd paste+0 mask+0: 1(-4.4,3.75) 2(-4.4,3.25) 3(-4.4,2.75) 4(-4.4,2.25) 5(-4.4,1.75) 6(-4.4,1.25) 7(-4.4,0.75) 8(-4.4,0.25) 9(-4.4,-0.25) 10(-4.4,-0.75) 11(-4.4,-1.25) 12(-4.4,-1.75) 13(-4.4,-2.25) 14(-4.4,-2.75) 15(-4.4,-3.25) 16(-4.4,-3.75) 33(4.4,-3.75) 34(4.4,-3.25) 35(4.4,-2.75) 36(4.4,-2.25) 37(4.4,-1.75) 38(4.4,-1.25) 39(4.4,-0.75) 40(4.4,-0.25) 41(4.4,0.25) 42(4.4,0.75) 43(4.4,1.25) 44(4.4,1.75) 45(4.4,2.25) 46(4.4,2.75) 47(4.4,3.25) 48(4.4,3.75)
  rrect42% 0.24x0.6 smd paste+0 mask+0: 17(-3.75,-4.4) 18(-3.25,-4.4) 19(-2.75,-4.4) 20(-2.25,-4.4) 21(-1.75,-4.4) 22(-1.25,-4.4) 23(-0.75,-4.4) 24(-0.25,-4.4) 25(0.25,-4.4) 26(0.75,-4.4) 27(1.25,-4.4) 28(1.75,-4.4) 29(2.25,-4.4) 30(2.75,-4.4) 31(3.25,-4.4) 32(3.75,-4.4) 49(3.75,4.4) 50(3.25,4.4) 51(2.75,4.4) 52(2.25,4.4) 53(1.75,4.4) 54(1.25,4.4) 55(0.75,4.4) 56(0.25,4.4) 57(-0.25,4.4) 58(-0.75,4.4) 59(-1.25,4.4) 60(-1.75,4.4) 61(-2.25,4.4) 62(-2.75,4.4) 63(-3.25,4.4) 64(-3.75,4.4)
  rrect1% 6.85x6.85 smd paste-1000 mask+0: 65(0,0)
  silkscreen extent -5.37,-4.55 4.55,4.55, body extent -4.8,-4.8 4.8,4.8, height 0.25
Samtec_HTSW-102-07-G-S [mm] "Samtec 100mil, 1x2, 230 mil above insulator"
  rrect6% 1.65x1.65 hole 1.016: 1(-1.27,0)
  round 1.65 hole 1.016: 2(1.27,0)
  silkscreen extent -3.3,-1.27 2.54,1.27, body extent -2.54,-1.27 2.54,1.27, height 8.38
Samtec_HTSW-103-07-G-S [mm] "Samtec 100mil, 1x3, 230 mil above insulator"
  rrect6% 1.65x1.65 hole 1.016: 1(-2.54,0)
  round 1.65 hole 1.016: 2(0,0) 3(2.54,0)
  silkscreen extent -4.57,-1.27 3.81,1.27, body extent -3.81,-1.27 3.81,1.27, height 8.38
SM_RADIAL_J16 [mm] "16 x 16.5mm:  Panasonic J16"
  rect 6.5x2.5 smd: 1(-6.25,0) 2(6.25,0)
  silkscreen extent -8.6,-8.6 8.6,8.6, body extent -8.6,-8.6 8.6,8.6, height 17
SOD-523 [mm] "NXP Semiconductor recommended land pattern, nominal STEP model"
  rect 0.8x0.6 smd paste-0.05: 1(-0.55,0) 2(0.55,0)
  silkscreen extent -1.65,-0.66 1.2,0.66, body extent -0.8,-0.4 0.8,0.4, height 0.72
SOT-23 [mm] "SOT23, 3-Leads, Body 2.9x1.3mm, Pitch 0.95mm, Lead Span 2.5mm, IPC Medium Density"
  rrect50% 1x0.6 smd: 1(-1.2,0.95) 2(-1.2,-0.95) 3(1.2,0)
  silkscreen extent -1.63,-1.5 0.7,1.5, body extent -1.16,-1.45 1.21,1.45, height 1
TI_Stacked_Overlay_Small [mil]
  silkscreen extent -418,-98 418,98
VBE0015A-MFG [mm]
  round 0.265 smd paste+0 mask-1000: 1(-1.675,2.875) 11(1.675,2.875)
  rrect40% 0.7x0.25 smd paste+0 mask-1000: 2(-1.85,2.325) 3(-1.85,1.825) 4(-1.85,1.325) 5(-1.85,0.825) 8(1.85,1.325) 9(1.85,1.825) 10(1.85,2.325)
  rrect11% 1.9x3.95 smd paste-1000 mask-1000: 6(-1.3,-1.525) 7(1.3,-1.525)
  rrect40% 0.25x0.7 smd paste+0 mask-1000: 12(0.575,3.1) 13(0.075,3.1) 14(-0.425,3.1) 15(-0.925,3.1)
  Top Layer region: -2.15,2.7 -2.169,2.704 -2.185,2.715 -2.196,2.731 -2.2,2.75 -2.2,2.75 -2.2,2.9 -2.193,2.925 -2.175,2.943 -2.15,2.95 -2.15,2.95 -1.85,2.95 -1.812,2.958 -1.779,2.979 -1.758,3.012 -1.75,3.05 -1.75,3.05 -1.75,3.4 -1.746,3.419 -1.735,3.435 -1.719,3.446 -1.7,3.45 -1.7,3.45 -1.55,3.45 -1.531,3.446 -1.515,3.435 -1.504,3.419 -1.5,3.4 -1.5,3.4 -1.5,2.75 -1.504,2.731 -1.515,2.715 -1.531,2.704 -1.55,2.7 -1.55,2.7
  Top Layer region: 2.15,2.7 2.169,2.704 2.185,2.715 2.196,2.731 2.2,2.75 2.2,2.75 2.2,2.9 2.193,2.925 2.175,2.943 2.15,2.95 2.15,2.95 1.85,2.95 1.812,2.958 1.779,2.979 1.758,3.012 1.75,3.05 1.75,3.05 1.75,3.4 1.746,3.419 1.735,3.435 1.719,3.446 1.7,3.45 1.7,3.45 1.55,3.45 1.531,3.446 1.515,3.435 1.504,3.419 1.5,3.4 1.5,3.4 1.5,2.75 1.504,2.731 1.515,2.715 1.531,2.704 1.55,2.7 1.55,2.7
  silkscreen extent -2.93,-3.55 2.35,3.55, body extent -2.35,-3.6 2.35,3.55, height 0.25
WEEE_Minimum [mil] "WEEElie bin"
  silkscreen extent -95,-172 99,104
WL-SMCW_GREEN [mm] "WURTH"
  rect 0.8x0.8 smd: 1(-0.8,0) 2(0.8,0)
  silkscreen extent -1.9,-0.8 1.2,0.8, body extent -0.85,-0.45 0.85,0.45, height 0.8
Wurth_60900213421 [mil] "Shunt, 2.54mm, Black"
  round 1 on Mech3: 0(0,0)
  body extent -98,-48 98,48, height 338
XAL1580 [mm] "COILCRAFT"
  rect 3.18x14.36 smd: 1(-5.3,0) 2(5.3,0)
  silkscreen extent -7.7,-7.8 7.7,7.8, body extent -7.7,-7.8 7.7,7.8, height 8

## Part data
C1: library part CMP-0011222-2, "CAP, AL, 150 uF, 100 V, +/- 20%, 0.17 ohm, AEC-Q200 Grade 2, SMD", Cap_Case=J16, Manufacturer=Panasonic, Supplier Part Number 1=PCE3499CT-ND, Tolerance_%=20%, Value1="0.17 ohm", Value2=100V, ValueDisplayed=150uF
C2_1 C2_2 C2_3 C2_4 C4_1 C4_2 C4_3 C4_4 C6_1 C6_2 C6_3 C6_4 C9_1 C9_2 C9_3 C9_4 C74 C75 C76 C77 C78 C79: library part CMP-0087970-1, "10µF ±10% 100V Ceramic Capacitor X7S 1210 (3225 Metric)", Manufacturer=Murata, TempCo=22%, Tolerance_%=10%, ValueDisplayed=10uF
C3_1 C3_2 C3_3 C3_4 C8_1 C8_2 C8_3 C8_4 C72 C73 C80 C81: library part CMP-0007469-4, "CAP, CERM, 0.1 uF, 100 V, +/- 10%, X7R, 0603", Cap_Case=0603, Manufacturer=MuRata, Supplier Part Number 1=490-3285-1-ND, TempCo=X7R, Tolerance_%=10%, Value1=Unknown, Value2=100V, ValueDisplayed=0.1uF
C5_1 C5_2 C5_3 C5_4 C7_1 C7_2 C7_3 C7_4 C91: library part CMP-0007891-2, "CAP, CERM, 1 uF, 100 V, +/- 10%, X7S, 0805", Cap_Case=0805, Manufacturer=TDK, Supplier Part Number 1=445-5205-1-ND, TempCo=X7S, Tolerance_%=10%, Value1="0.008255 ohm", Value2=100V, ValueDisplayed=1uF
C10 C13_1 C13_2 C13_3 C13_4 C16_1 C16_2 C16_3 C16_4 C17_1 C17_2 C17_3 C17_4 C20_1 C20_2 C20_3 C20_4 C21_1 C21_2 C21_3 C21_4 C22 C23_1 C23_2 C23_3 C23_4 C24_1 C24_2 C24_3 C24_4 C25 C26 C27 C29_1 C29_2 C29_3 C29_4 C31_1 C31_2 C31_3 C31_4 C33_1 C33_2 C33_3 C33_4 C35 C36 C37 C38 C39 C40 C55 C62 C64 C65 C66 C67 C69 C71 C83 C90 C93 C96 C98 C99 C104 C105 C109 C115_1 C115_2 C115_3 C115_4 C117 C118 C119 C120 C121 C123 C124 C125 C126 C127 C128 C129 C130 C131 C132 C133 C134 C135 C136: library part CMP-0006591-2, "CAP, CERM, 0.1 uF, 16 V, +/- 10%, X5R, 0402", Cap_Case=0402, Manufacturer=MuRata, Supplier Part Number 1=490-5415-1-ND, TempCo=X5R, Tolerance_%=10%, Value1=Unknown, Value2=16V, ValueDisplayed=0.1uF
C11_1 C11_2 C11_3 C11_4 C12_1 C12_2 C12_3 C12_4 C14_1 C14_2 C14_3 C14_4 C15_1 C15_2 C15_3 C15_4: library part CMP-0009201-2, "CAP, CERM, 47 uF, 16 V, +/- 20%, X6S, 1210", Cap_Case=1210, Manufacturer=MuRata, Supplier Part Number 1=490-9968-1-ND, TempCo=X6S, Tolerance_%=20%, Value1=Unknown, Value2=16V, ValueDisplayed=47uF
C18_1 C18_2 C18_3 C18_4: library part CMP-0008093-2, "CAP, CERM, 100 pF, 100 V, +/- 5%, C0G/NP0, 0805", Cap_Case=0805, Manufacturer=MuRata, Supplier Part Number 1=490-1599-1-ND, TempCo=C0G/NP0, Tolerance_%=5%, Value1=Unknown, Value2=100V, ValueDisplayed=100pF
C19_1 C19_2 C19_3 C19_4 C30_1 C30_2 C30_3 C30_4 C44 C45 C46 C47 C57 C58 C60 C61 C84 C85 C89: library part CMP-0076705-3, "CAP, CERM, 1 µF, 25 V,+/- 10%, X7R, AEC-Q200 Grade 1, 0603", Cap_Case=1.6x0.8x0.8mm, Manufacturer=TDK, Supplier Part Number 1=445-6931-1-ND, TempCo=X7R, Tolerance_%=10%, Value2=25V, ValueDisplayed=1µF
C28_1 C28_2 C28_3 C28_4 C68 C97 C100 C101 C102 C103 C106 C107 C108 C114_1 C114_2 C114_3 C114_4: library part CMP-0006711-2, "CAP, CERM, 470 pF, 100 V, +/- 10%, X7R, 0402", Cap_Case=0402, Manufacturer=MuRata, Supplier Part Number 1=GRM155R72A471KA01D-ND, TempCo=X7R, Tolerance_%=10%, Value1=Unknown, Value2=100V, ValueDisplayed=470pF
C32_1 C32_2 C32_3 C32_4 C34_1 C34_2 C34_3 C34_4: library part CMP-0008309-2, "CAP, CERM, 4.7 uF, 50 V, +/- 10%, X5R, 0805", Cap_Case=0805, Manufacturer=MuRata, Supplier Part Number 1=GRM21BR61H475KE51L-ND, TempCo=X5R, Tolerance_%=10%, Value1=Unknown, Value2=50V, ValueDisplayed=4.7uF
